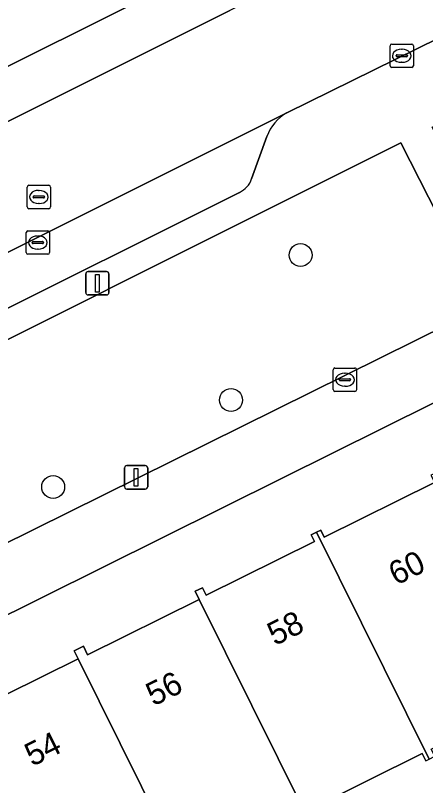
# Model space of a CAD drawing. Extents: x 157793 to 159380, y 380877 to 382313.
# Drawn here: x 158355.06 to 158372.58, y 381486.85 to 381519.79 of the extents above; entities that cross this region are included whole.
import ezdxf

# ---------------------------------------------------------------- set-up
doc = ezdxf.new("R2010")
doc.units = 0
for name, color, linetype in [('IMGEO_Boom', 7, 'Continuous'), ('IMGEO_Erf', 7, 'Continuous'), ('IMGEO_Groenvoorziening', 7, 'Continuous'), ('IMGEO_Kolk', 7, 'Continuous'), ('IMGEO_Lichtmast', 7, 'Continuous'), ('IMGEO_Pand', 7, 'Continuous'), ('IMGEO_Pand_nummerreeks', 7, 'Continuous'), ('IMGEO_Parkeervlak_open', 7, 'Continuous'), ('IMGEO_Rijbaan_lokaal_open', 7, 'Continuous'), ('IMGEO_Rioolput', 7, 'Continuous'), ('IMGEO_Voetpad_open', 7, 'Continuous')]:
    doc.layers.add(name, color=color, linetype=linetype)

msp = doc.modelspace()

# ---------------------------------------------------------------- linework, layer by layer
at = {"layer": 'IMGEO_Boom'}
for centre in [(158367.239, 381509.541), (158364.268, 381503.342), (158356.671, 381499.625)]:
    msp.add_circle(centre, 0.489, dxfattribs=at)
at = {"layer": 'IMGEO_Erf'}
for points in [[(158402.954, 381518.145), (158366.45, 381500), (158351.122, 381492.381), (158352.463, 381489.666), (158352.708, 381489.787), (158352.537, 381490.13), (158352.93, 381490.325), (158353.102, 381489.979), (158357.737, 381492.281), (158357.573, 381492.618), (158357.962, 381492.811), (158358.143, 381492.448), (158362.913, 381494.818), (158362.742, 381495.162), (158363.054, 381495.317), (158363.213, 381494.997), (158367.837, 381497.294), (158367.696, 381497.579), (158367.923, 381497.692), (158368.1, 381497.78), (158368.25, 381497.478), (158372.968, 381499.822)], [(158372.592, 381487.918), (158372.437, 381488.23), (158367.788, 381485.921), (158367.943, 381485.61), (158367.574, 381485.427), (158367.413, 381485.746), (158362.656, 381483.383), (158362.812, 381483.07), (158362.474, 381482.902), (158362.245, 381483.192), (158357.557, 381480.863), (158357.73, 381480.516), (158357.387, 381480.346), (158357.187, 381480.75), (158356.951, 381480.633), (158362.318, 381469.832), (158363.718, 381470.564), (158362.75, 381472.409), (158362.128, 381473.594), (158365.998, 381475.625), (158369.472, 381477.447), (158371.062, 381474.417), (158374.236, 381475.815)]]:
    msp.add_lwpolyline(points, dxfattribs=at)
at = {"layer": 'IMGEO_Groenvoorziening'}
msp.add_lwpolyline([(158375.088, 381507.338), (158371.522, 381514.342), (158346.435, 381501.779), (158349.93, 381494.878)], close=True, dxfattribs=at)
at = {"layer": 'IMGEO_Kolk'}
for p, q in [((158371.061, 381517.639), (158371.061, 381518.491)), ((158371.136, 381518.565), (158371.988, 381518.565)), ((158372.062, 381518.491), (158372.062, 381517.639)), ((158371.549, 381518.345), (158371.574, 381518.345)), ((158371.32, 381518.059), (158371.32, 381518.071)), ((158371.758, 381518.022), (158371.36, 381518.022)), ((158371.363, 381518.108), (158371.761, 381518.108)), ((158371.804, 381518.071), (158371.804, 381518.059)), ((158371.988, 381517.565), (158371.136, 381517.565)), ((158371.572, 381517.785), (158371.547, 381517.785)), ((158355.592, 381510.576), (158356.444, 381510.576)), ((158355.517, 381509.65), (158355.517, 381510.502)), ((158356.005, 381510.356), (158356.03, 381510.356)), ((158356.518, 381510.502), (158356.518, 381509.65)), ((158355.776, 381510.07), (158355.776, 381510.082)), ((158356.214, 381510.033), (158355.816, 381510.033)), ((158355.819, 381510.119), (158356.217, 381510.119)), ((158356.26, 381510.082), (158356.26, 381510.07)), ((158356.444, 381509.576), (158355.592, 381509.576)), ((158356.028, 381509.796), (158356.003, 381509.796)), ((158368.635, 381503.786), (158368.635, 381504.638)), ((158368.71, 381504.712), (158369.562, 381504.712)), ((158369.636, 381504.638), (158369.636, 381503.786)), ((158369.123, 381504.492), (158369.148, 381504.492)), ((158368.894, 381504.206), (158368.894, 381504.218)), ((158369.332, 381504.169), (158368.934, 381504.169)), ((158368.937, 381504.255), (158369.335, 381504.255)), ((158369.378, 381504.218), (158369.378, 381504.206)), ((158369.562, 381503.712), (158368.71, 381503.712)), ((158369.146, 381503.932), (158369.121, 381503.932))]:
    msp.add_line(p, q, dxfattribs=at)
for points in [[(158371.061, 381517.639), (158371.061, 381518.491)], [(158371.136, 381518.565), (158371.988, 381518.565)], [(158372.062, 381518.491), (158372.062, 381517.639)], [(158371.988, 381517.565), (158371.136, 381517.565)], [(158355.592, 381510.576), (158356.444, 381510.576)], [(158355.517, 381509.65), (158355.517, 381510.502)], [(158356.518, 381510.502), (158356.518, 381509.65)], [(158356.444, 381509.576), (158355.592, 381509.576)], [(158368.635, 381503.786), (158368.635, 381504.638)], [(158368.71, 381504.712), (158369.562, 381504.712)], [(158369.636, 381504.638), (158369.636, 381503.786)], [(158369.562, 381503.712), (158368.71, 381503.712)]]:
    msp.add_lwpolyline(points, dxfattribs=at)
for centre, radius, start, end in [((158371.138, 381518.489), 0.0765, 91.552, 178.448), ((158371.138, 381518.489), 0.0765, 91.552, 178.448), ((158371.986, 381518.489), 0.0765, 1.552, 88.448), ((158371.986, 381518.489), 0.0765, 1.552, 88.448), ((158371.36, 381518.068), 0.0403, 85.8775, 175.7526), ((158371.357, 381518.058), 0.0366, 178.938, 274.7102), ((158371.761, 381518.065), 0.043, 264.8664, 352.4533), ((158371.765, 381518.07), 0.0386, 1.7309, 96.639), ((158371.138, 381517.641), 0.0765, 181.552, 268.448), ((158371.138, 381517.641), 0.0765, 181.552, 268.448), ((158371.986, 381517.641), 0.0765, 271.552, 358.448), ((158371.986, 381517.641), 0.0765, 271.552, 358.448), ((158355.594, 381510.5), 0.0765, 91.552, 178.448), ((158355.594, 381510.5), 0.0765, 91.552, 178.448), ((158356.442, 381510.5), 0.0765, 1.552, 88.448), ((158356.442, 381510.5), 0.0765, 1.552, 88.448), ((158355.816, 381510.079), 0.0403, 85.8775, 175.7526), ((158355.813, 381510.069), 0.0366, 178.938, 274.7102), ((158356.217, 381510.076), 0.043, 264.8664, 352.4533), ((158356.221, 381510.081), 0.0386, 1.7309, 96.639), ((158355.594, 381509.652), 0.0765, 181.552, 268.448), ((158355.594, 381509.652), 0.0765, 181.552, 268.448), ((158356.442, 381509.652), 0.0765, 271.552, 358.448), ((158356.442, 381509.652), 0.0765, 271.552, 358.448), ((158368.712, 381504.636), 0.0765, 91.552, 178.448), ((158368.712, 381504.636), 0.0765, 91.552, 178.448), ((158369.56, 381504.636), 0.0765, 1.552, 88.448), ((158369.56, 381504.636), 0.0765, 1.552, 88.448), ((158368.934, 381504.215), 0.0403, 85.8775, 175.7526), ((158368.931, 381504.205), 0.0366, 178.938, 274.7102), ((158369.335, 381504.212), 0.043, 264.8664, 352.4533), ((158369.339, 381504.217), 0.0386, 1.7309, 96.639), ((158368.712, 381503.788), 0.0765, 181.552, 268.448), ((158368.712, 381503.788), 0.0765, 181.552, 268.448), ((158369.56, 381503.788), 0.0765, 271.552, 358.448), ((158369.56, 381503.788), 0.0765, 271.552, 358.448)]:
    msp.add_arc(centre, radius, start, end, dxfattribs=at)
for centre, major_axis, ratio, start_param, end_param in [((158371.548, 381518.065), (-0.387, 0.002), 0.722429, 4.712389, 7.853982), ((158371.573, 381518.065), (-0.39, 0.002), 0.717154, 1.570796, 4.712389), ((158356.004, 381510.076), (-0.387, 0.002), 0.722429, 4.712389, 7.853982), ((158356.029, 381510.076), (-0.39, 0.002), 0.717154, 1.570796, 4.712389), ((158369.122, 381504.212), (-0.387, 0.002), 0.722429, 4.712389, 7.853982), ((158369.147, 381504.212), (-0.39, 0.002), 0.717154, 1.570796, 4.712389)]:
    msp.add_ellipse(centre, major_axis=major_axis, ratio=ratio, start_param=start_param, end_param=end_param, dxfattribs=at)
at = {"layer": 'IMGEO_Lichtmast'}
for p, q in [((158358.065, 381507.935), (158358.065, 381508.735)), ((158358.065, 381508.735), (158358.065, 381507.935)), ((158358.165, 381508.835), (158358.955, 381508.835)), ((158358.955, 381508.835), (158358.165, 381508.835)), ((158359.055, 381508.735), (158359.055, 381507.935)), ((158359.055, 381507.935), (158359.055, 381508.735)), ((158358.955, 381507.835), (158358.165, 381507.835)), ((158358.165, 381507.835), (158358.955, 381507.835)), ((158359.718, 381499.637), (158359.718, 381500.437)), ((158359.718, 381500.437), (158359.718, 381499.637)), ((158359.818, 381500.537), (158360.608, 381500.537)), ((158360.608, 381500.537), (158359.818, 381500.537)), ((158360.708, 381500.437), (158360.708, 381499.637)), ((158360.708, 381499.637), (158360.708, 381500.437)), ((158360.608, 381499.537), (158359.818, 381499.537)), ((158359.818, 381499.537), (158360.608, 381499.537))]:
    msp.add_line(p, q, dxfattribs=at)
for points in [[(158358.485, 381508.71), (158358.635, 381508.71), (158358.635, 381507.96), (158358.485, 381507.96), (158358.485, 381508.71)], [(158360.138, 381500.412), (158360.288, 381500.412), (158360.288, 381499.662), (158360.138, 381499.662), (158360.138, 381500.412)]]:
    msp.add_lwpolyline(points, dxfattribs=at)
for centre, start, end in [((158358.165, 381508.735), 90, 180), ((158358.165, 381508.735), 90, 180), ((158358.955, 381508.735), 0, 90), ((158358.955, 381508.735), 360, 90), ((158358.165, 381507.935), 180, 270), ((158358.165, 381507.935), 180, 270), ((158358.955, 381507.935), 270, 0), ((158358.955, 381507.935), 270, 0), ((158359.818, 381500.437), 90, 180), ((158359.818, 381500.437), 90, 180), ((158360.608, 381500.437), 0, 90), ((158360.608, 381500.437), 360, 90), ((158359.818, 381499.637), 180, 270), ((158359.818, 381499.637), 180, 270), ((158360.608, 381499.637), 270, 0), ((158360.608, 381499.637), 270, 0)]:
    msp.add_arc(centre, 0.1, start, end, dxfattribs=at)
at = {"layer": 'IMGEO_Pand'}
for points in [[(158367.923, 381497.692), (158372.735, 381487.989), (158372.972, 381488.107), (158372.821, 381488.41), (158377.582, 381490.775), (158377.735, 381490.467), (158377.9, 381490.549), (158373.212, 381500), (158373.088, 381500.249), (158372.803, 381500.124), (158372.871, 381500), (158372.968, 381499.822), (158368.25, 381497.478), (158368.1, 381497.78)], [(158367.923, 381497.692), (158367.696, 381497.579), (158367.837, 381497.294), (158363.213, 381494.997), (158363.054, 381495.317), (158362.742, 381495.162), (158362.913, 381494.818), (158367.413, 381485.746), (158367.574, 381485.427), (158367.943, 381485.61), (158367.788, 381485.921), (158372.437, 381488.23), (158372.592, 381487.918), (158372.735, 381487.989)], [(158362.913, 381494.818), (158358.143, 381492.448), (158357.962, 381492.811), (158357.573, 381492.618), (158357.737, 381492.281), (158362.245, 381483.192), (158362.474, 381482.902), (158362.812, 381483.07), (158362.656, 381483.383), (158367.413, 381485.746)], [(158362.245, 381483.192), (158357.737, 381492.281), (158353.102, 381489.979), (158352.93, 381490.325), (158352.537, 381490.13), (158352.708, 381489.787), (158352.463, 381489.666), (158354.687, 381485.189), (158356.951, 381480.633), (158357.187, 381480.75), (158357.387, 381480.346), (158357.73, 381480.516), (158357.557, 381480.863)]]:
    msp.add_lwpolyline(points, close=True, dxfattribs=at)
at = {"layer": 'IMGEO_Parkeervlak_open'}
for points in [[(158360.378, 381520.424), (158339.842, 381510.182), (158335.434, 381507.954), (158328.215, 381504.357), (158323.691, 381502.101), (158292.396, 381486.391), (158290.721, 381485.284)], [(158295.372, 381485.52), (158300.625, 381488.183), (158323.239, 381499.498), (158364.219, 381519.993)], [(158366.656, 381515.626), (158325.561, 381495.049)], [(158365.148, 381512.802), (158365.799, 381514.614)], [(158329.72, 381494.777), (158364.631, 381512.222)]]:
    msp.add_lwpolyline(points, dxfattribs=at)
for centre, radius, start, end in [((158367.585, 381513.971), 1.898, 119.2933, 160.1883), ((158364.212, 381513.116), 0.987, 295.1046, 341.4691)]:
    msp.add_arc(centre, radius, start, end, dxfattribs=at)
at = {"layer": 'IMGEO_Rijbaan_lokaal_open'}
msp.add_lwpolyline([(158429.532, 381546.784), (158430.537, 381547.261), (158428.291, 381551.786), (158422.95, 381549.11), (158406.043, 381540.758), (158405.49, 381540.487), (158405.162, 381540.325), (158390.456, 381533.119), (158390.104, 381532.932), (158364.219, 381519.993), (158323.239, 381499.498), (158325.561, 381495.049), (158366.656, 381515.626), (158376.866, 381520.672)], close=True, dxfattribs=at)
at = {"layer": 'IMGEO_Rioolput'}
for p, q in [((158355.56, 381511.599), (158355.56, 381512.451)), ((158355.635, 381512.525), (158356.487, 381512.525)), ((158356.048, 381512.305), (158356.073, 381512.305)), ((158356.561, 381512.451), (158356.561, 381511.599)), ((158355.819, 381512.019), (158355.819, 381512.031)), ((158356.257, 381511.982), (158355.859, 381511.982)), ((158355.862, 381512.068), (158356.26, 381512.068)), ((158356.303, 381512.031), (158356.303, 381512.019)), ((158356.071, 381511.745), (158356.046, 381511.745)), ((158356.487, 381511.525), (158355.635, 381511.525))]:
    msp.add_line(p, q, dxfattribs=at)
for points in [[(158355.56, 381511.599), (158355.56, 381512.451)], [(158355.635, 381512.525), (158356.487, 381512.525)], [(158356.561, 381512.451), (158356.561, 381511.599)], [(158356.487, 381511.525), (158355.635, 381511.525)]]:
    msp.add_lwpolyline(points, dxfattribs=at)
for centre, radius, start, end in [((158355.637, 381512.449), 0.0765, 91.552, 178.448), ((158355.637, 381512.449), 0.0765, 91.552, 178.448), ((158356.485, 381512.449), 0.0765, 1.552, 88.448), ((158356.485, 381512.449), 0.0765, 1.552, 88.448), ((158355.859, 381512.028), 0.0403, 85.8775, 175.7526), ((158355.856, 381512.018), 0.0366, 178.938, 274.7102), ((158356.26, 381512.025), 0.043, 264.8664, 352.4533), ((158356.264, 381512.03), 0.0386, 1.7309, 96.639), ((158355.637, 381511.601), 0.0765, 181.552, 268.448), ((158355.637, 381511.601), 0.0765, 181.552, 268.448), ((158356.485, 381511.601), 0.0765, 271.552, 358.448), ((158356.485, 381511.601), 0.0765, 271.552, 358.448)]:
    msp.add_arc(centre, radius, start, end, dxfattribs=at)
for centre, major_axis, ratio, start_param, end_param in [((158356.047, 381512.025), (-0.387, 0.002), 0.722429, 4.712389, 7.853982), ((158356.072, 381512.025), (-0.39, 0.002), 0.717154, 1.570796, 4.712389)]:
    msp.add_ellipse(centre, major_axis=major_axis, ratio=ratio, start_param=start_param, end_param=end_param, dxfattribs=at)
at = {"layer": 'IMGEO_Voetpad_open'}
for points in [[(158429.862, 381531.521), (158428.618, 381533.96), (158403, 381521.175), (158401.658, 381520.527), (158376.436, 381508.005), (158375.088, 381507.338), (158349.93, 381494.878), (158348.584, 381494.228), (158326.422, 381483.272), (158325.707, 381482.947)], [(158327.204, 381480.491), (158349.769, 381491.708), (158351.122, 381492.381), (158366.45, 381500), (158402.954, 381518.145), (158404.227, 381518.778), (158429.862, 381531.521)], [(158319.462, 381487.986), (158324.627, 381490.884), (158345.094, 381501.119), (158348.584, 381494.228), (158349.93, 381494.878), (158346.435, 381501.779), (158371.522, 381514.342), (158375.088, 381507.338), (158376.436, 381508.005), (158372.857, 381515.012), (158398.164, 381527.551)], [(158376.866, 381520.672), (158366.656, 381515.626)], [(158290.721, 381485.284), (158292.396, 381486.391), (158323.691, 381502.101), (158328.215, 381504.357), (158335.434, 381507.954), (158339.842, 381510.182), (158360.378, 381520.424)], [(158365.799, 381514.614), (158365.148, 381512.802)], [(158364.631, 381512.222), (158329.72, 381494.777)]]:
    msp.add_lwpolyline(points, dxfattribs=at)
for centre, radius, start, end in [((158367.585, 381513.971), 1.898, 119.2933, 160.1883), ((158364.212, 381513.116), 0.987, 295.1046, 341.4691)]:
    msp.add_arc(centre, radius, start, end, dxfattribs=at)

# ---------------------------------------------------------------- texts
at = {"layer": 'IMGEO_Pand_nummerreeks'}
for s, rotation, p in [('60', 26.4796, (158371.325, 381495.397)), ('58', 26.4821, (158366.143, 381492.816)), ('56', 26.4821, (158360.959, 381490.233)), ('54', 26.4796, (158355.777, 381487.652))]:
    msp.add_text(s, height=1, rotation=rotation, dxfattribs=at).set_placement(p)

doc.saveas('drawing.dxf')
